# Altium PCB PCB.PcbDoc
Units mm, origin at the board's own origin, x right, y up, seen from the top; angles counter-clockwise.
Board outline 52 x 43.5 mm, 4 copper layers (Top Copper, Signal Layer 1, Signal Layer 2, Bottom Copper), stack 1.57 mm thick; 27 components, 30 nets, 106 pads, 306 vias.
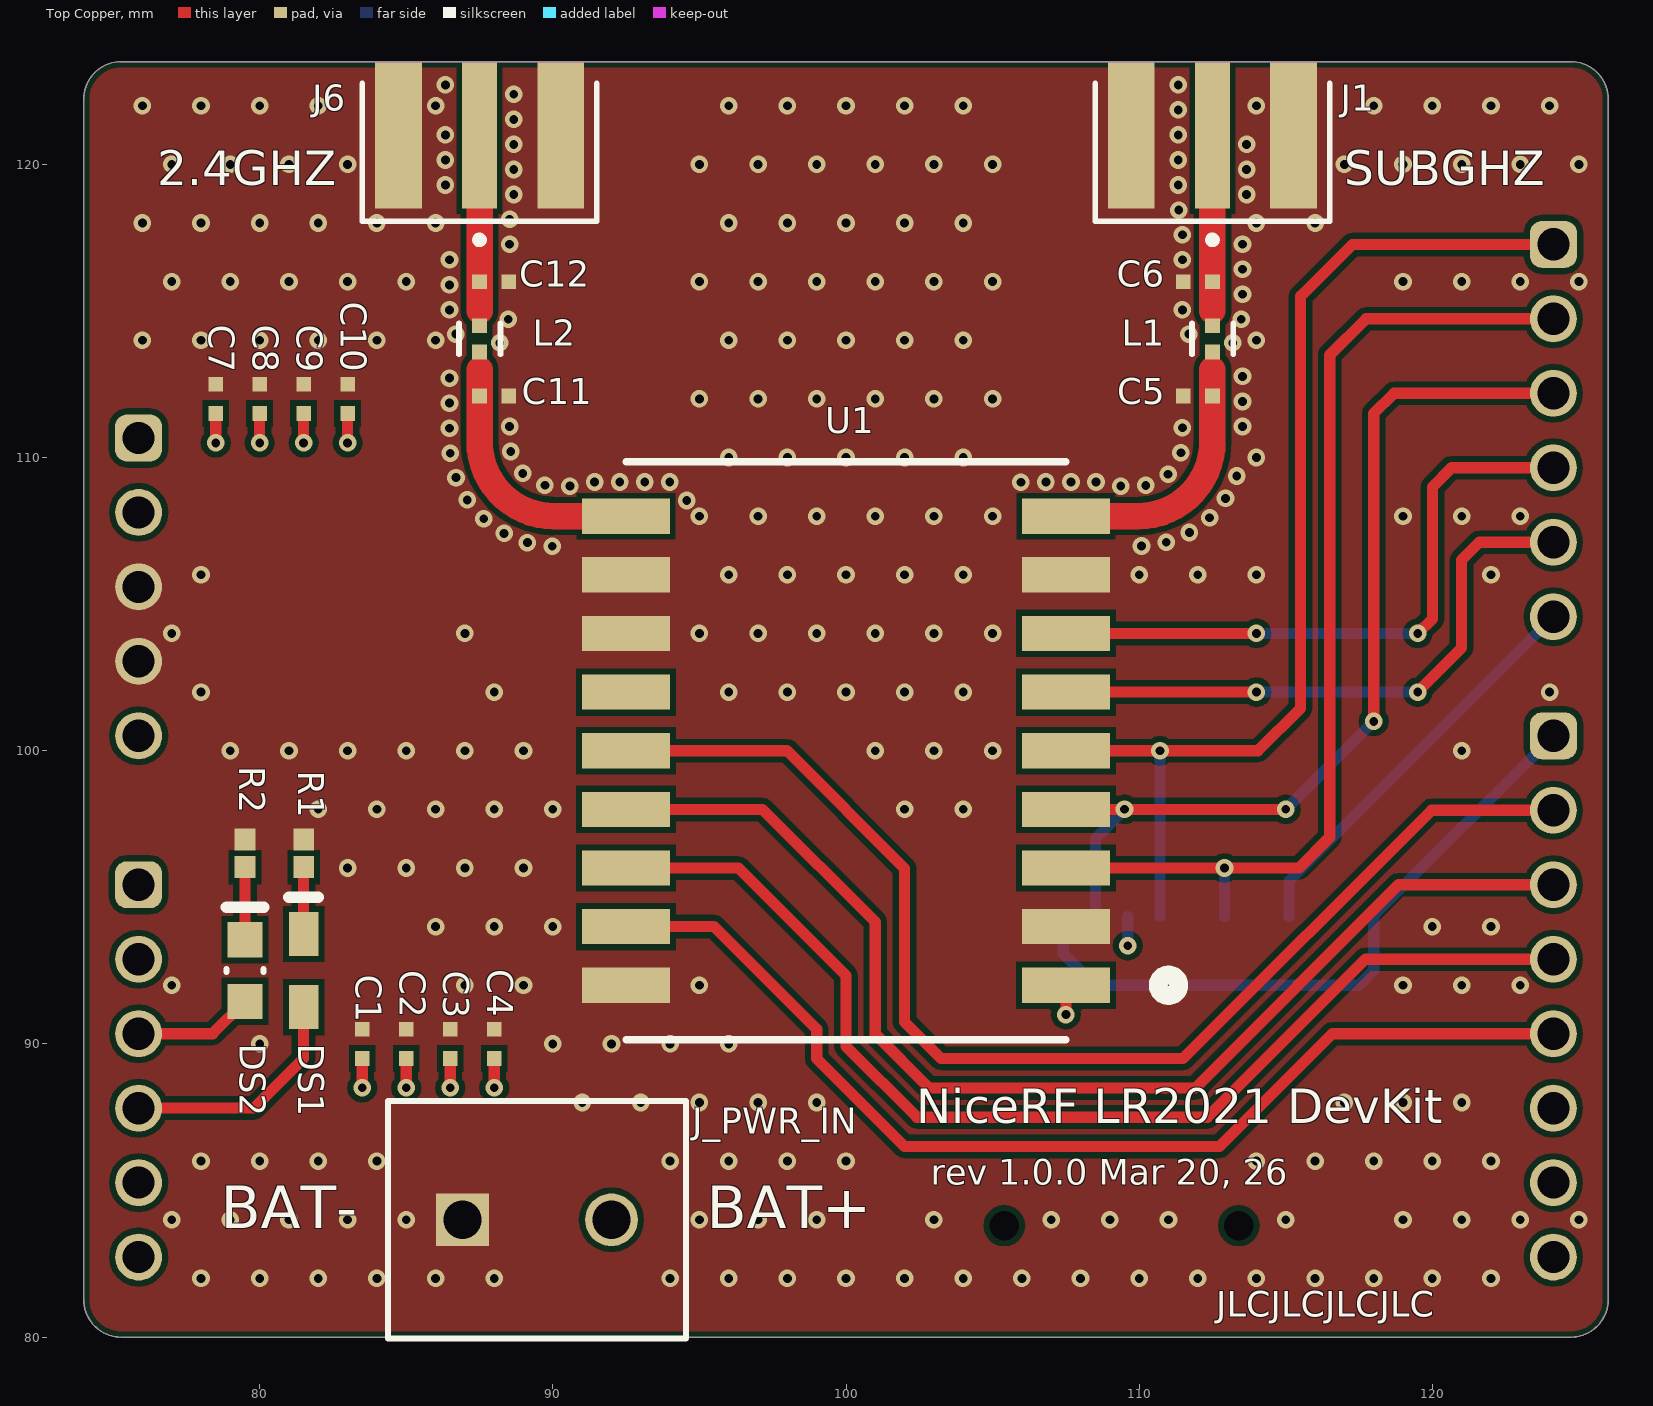
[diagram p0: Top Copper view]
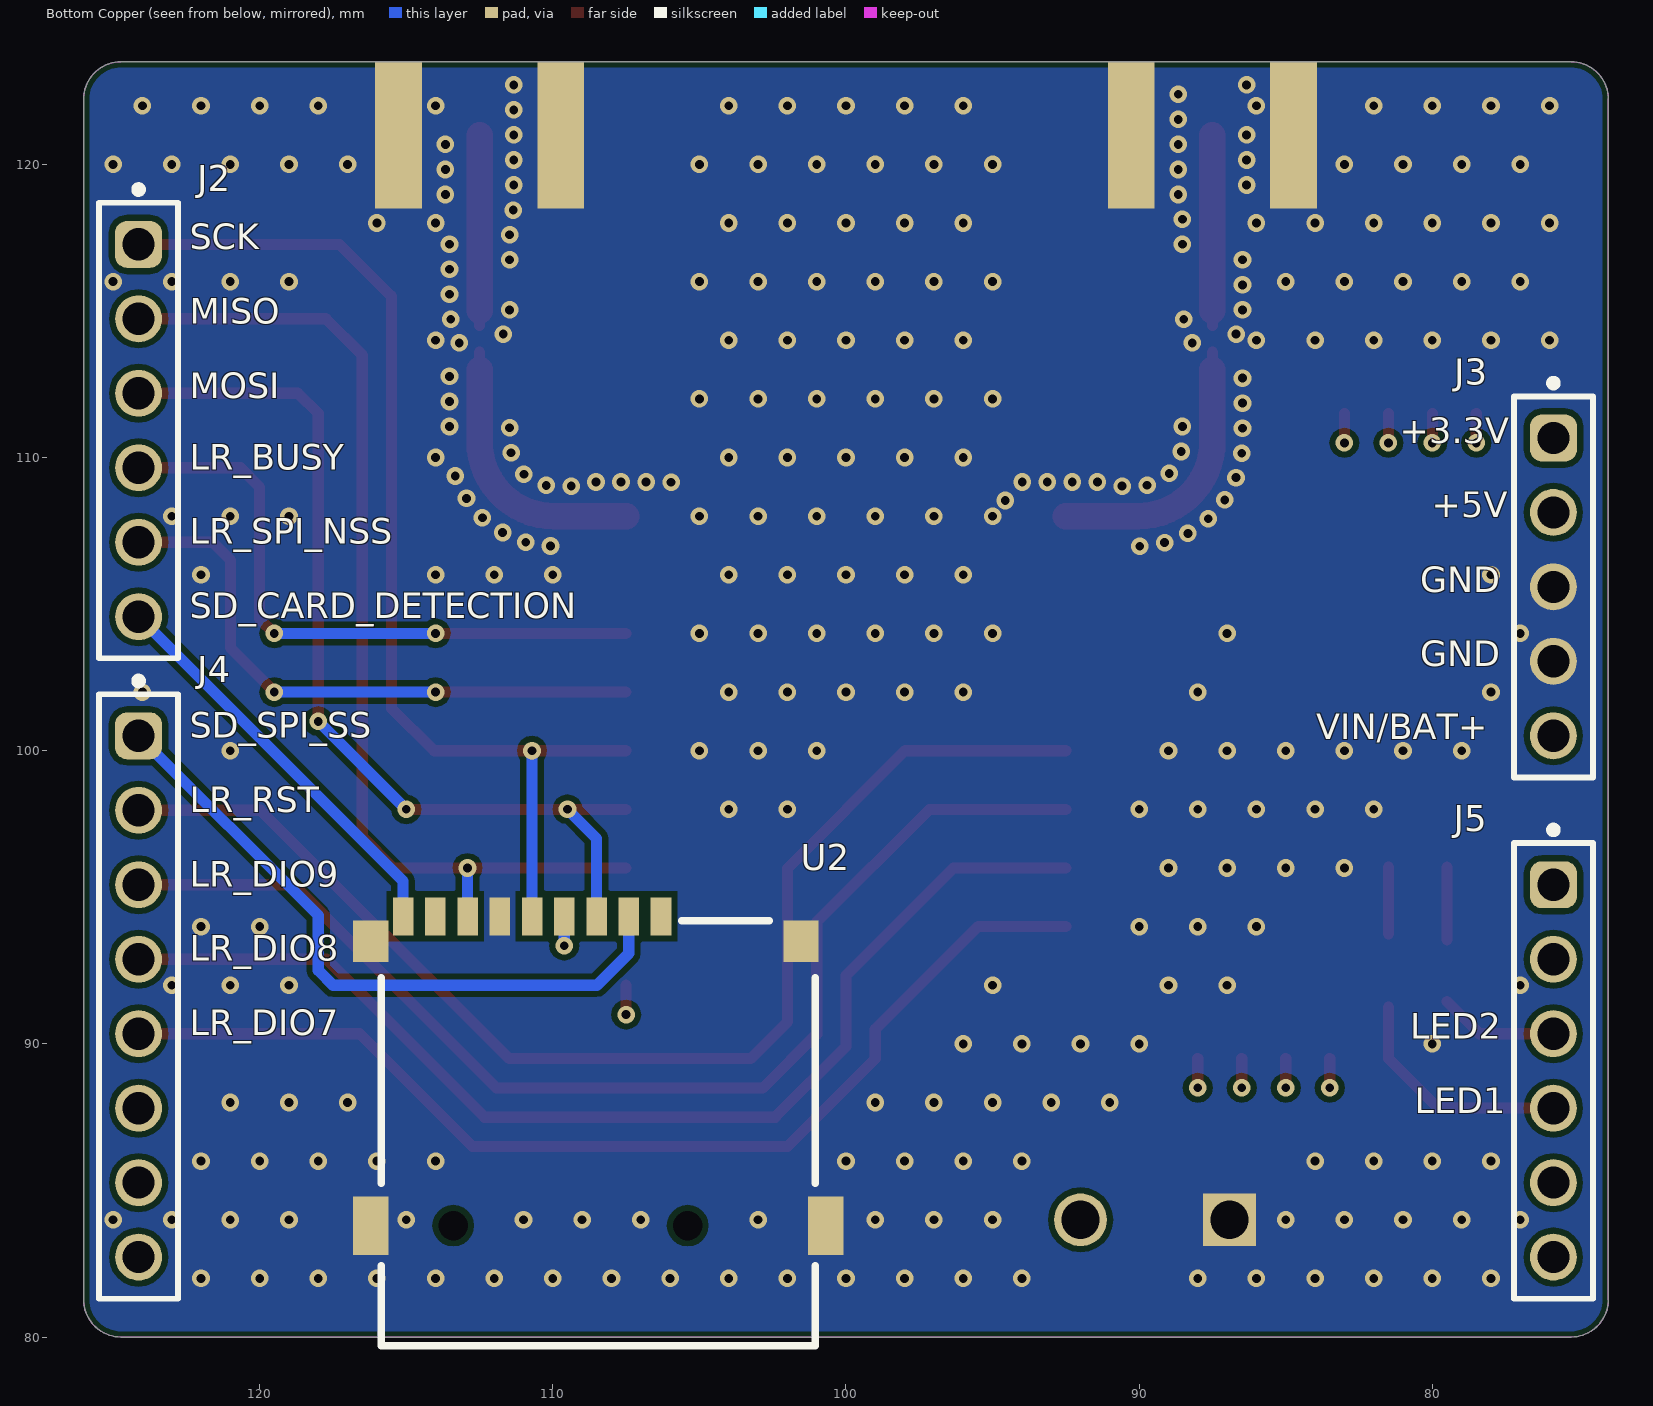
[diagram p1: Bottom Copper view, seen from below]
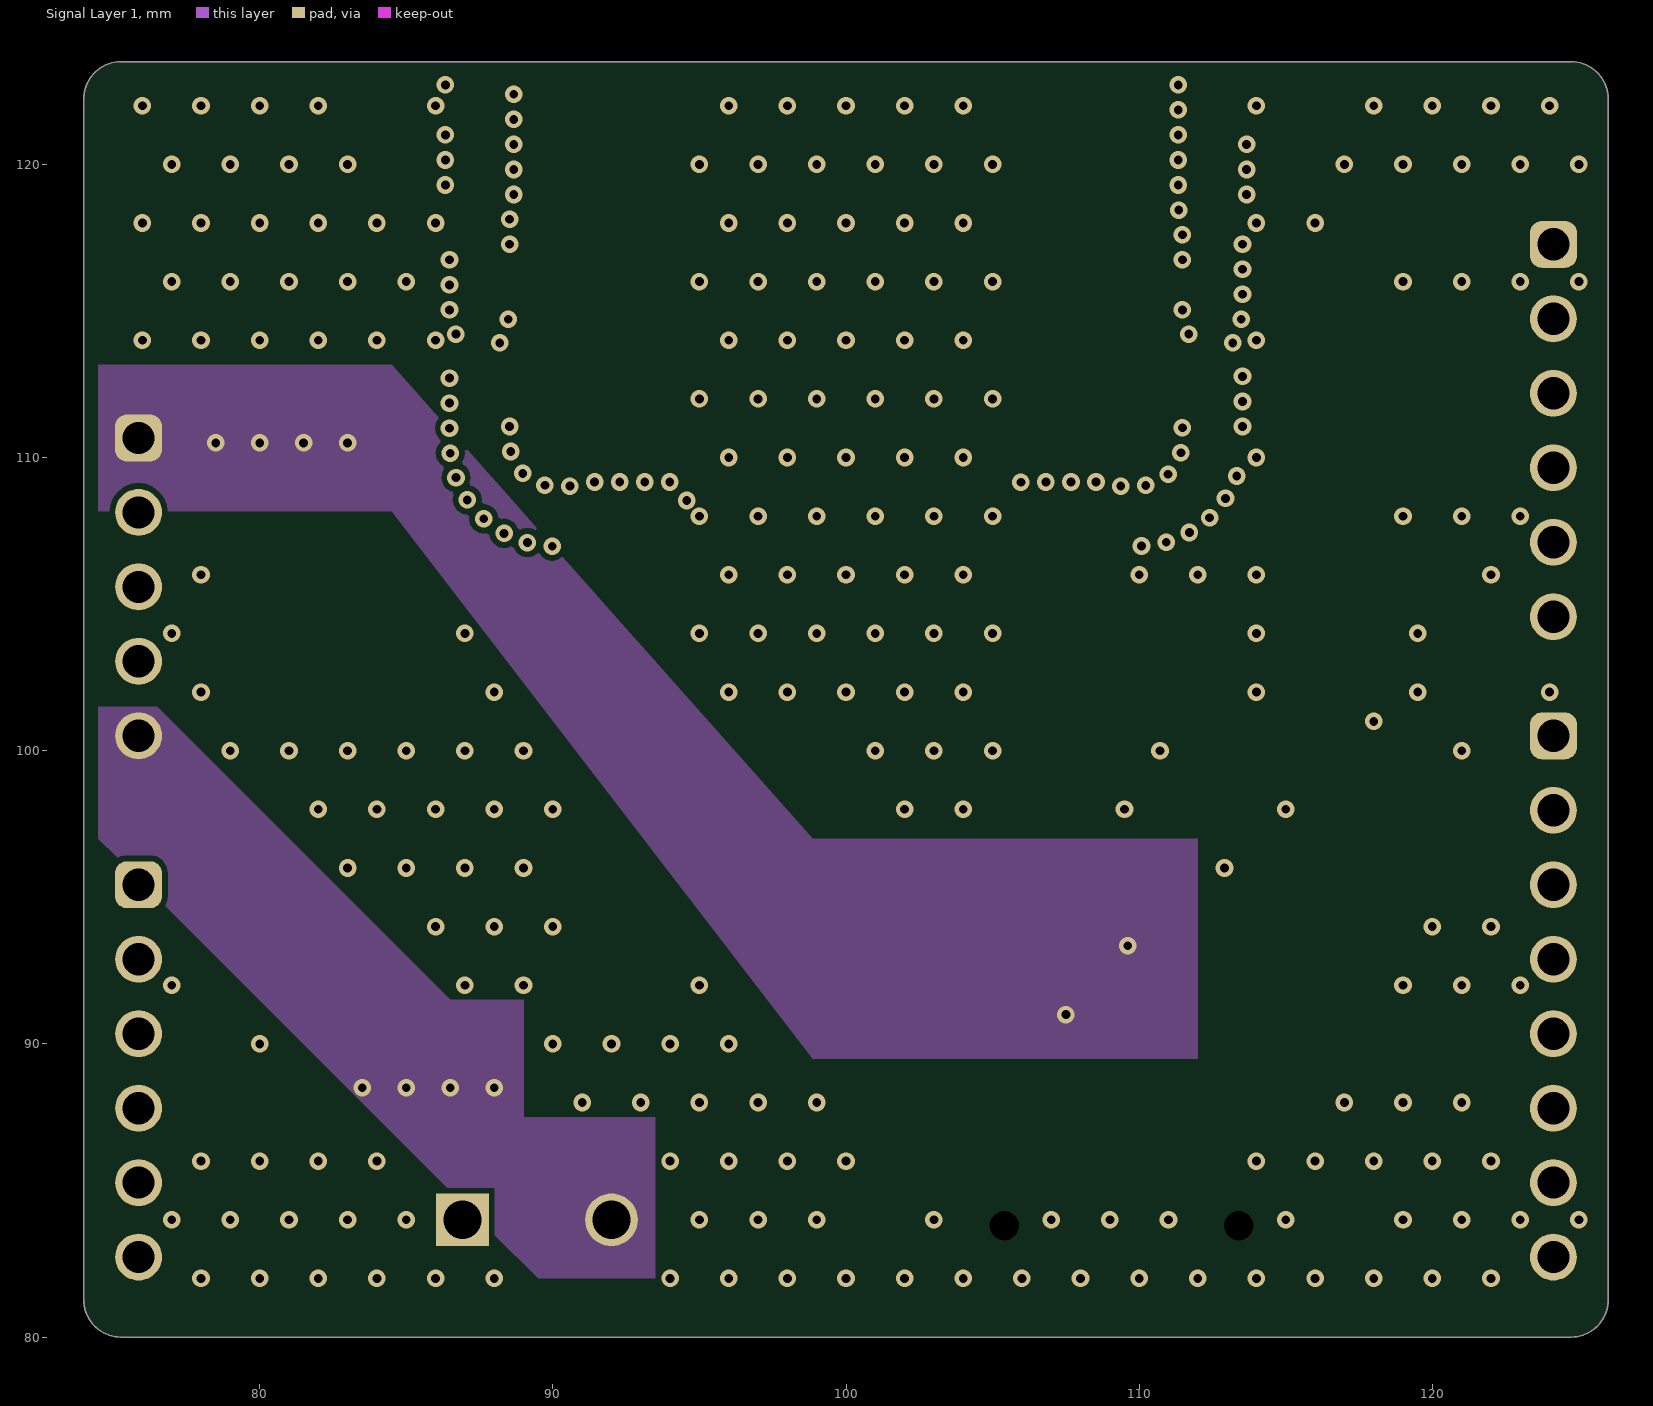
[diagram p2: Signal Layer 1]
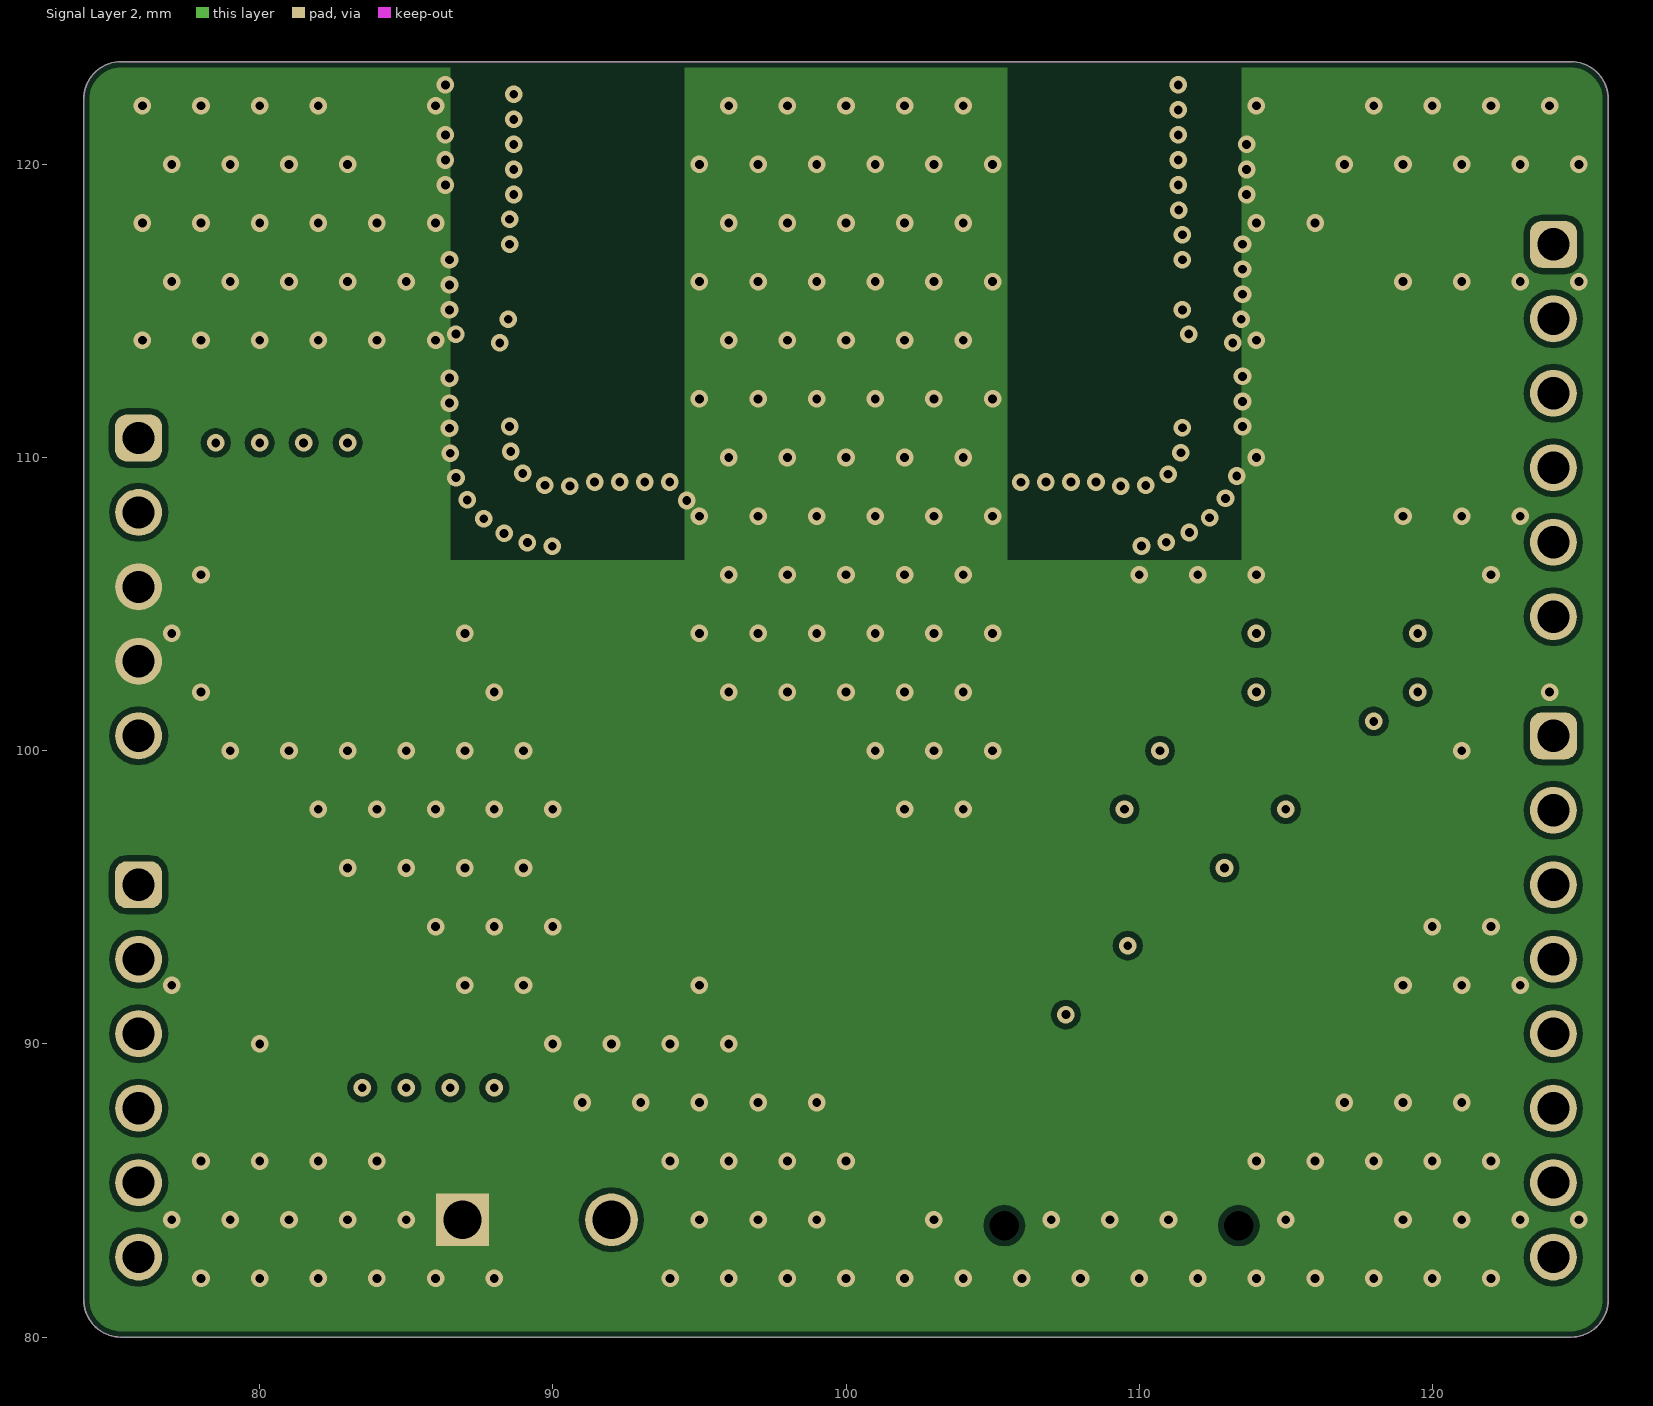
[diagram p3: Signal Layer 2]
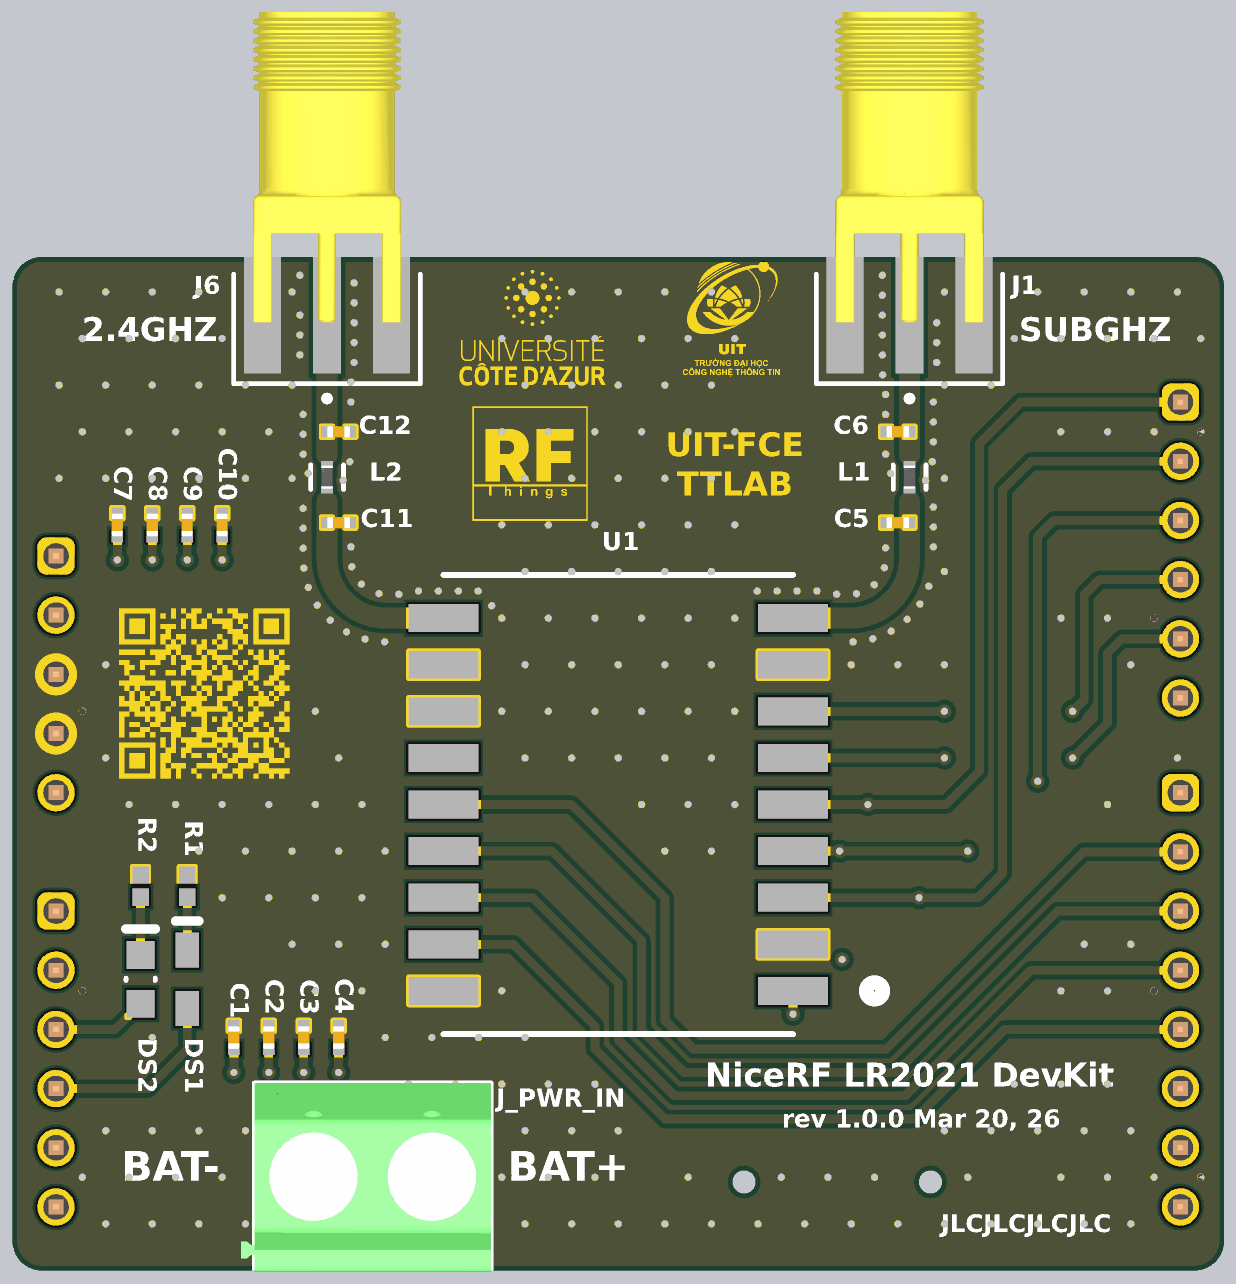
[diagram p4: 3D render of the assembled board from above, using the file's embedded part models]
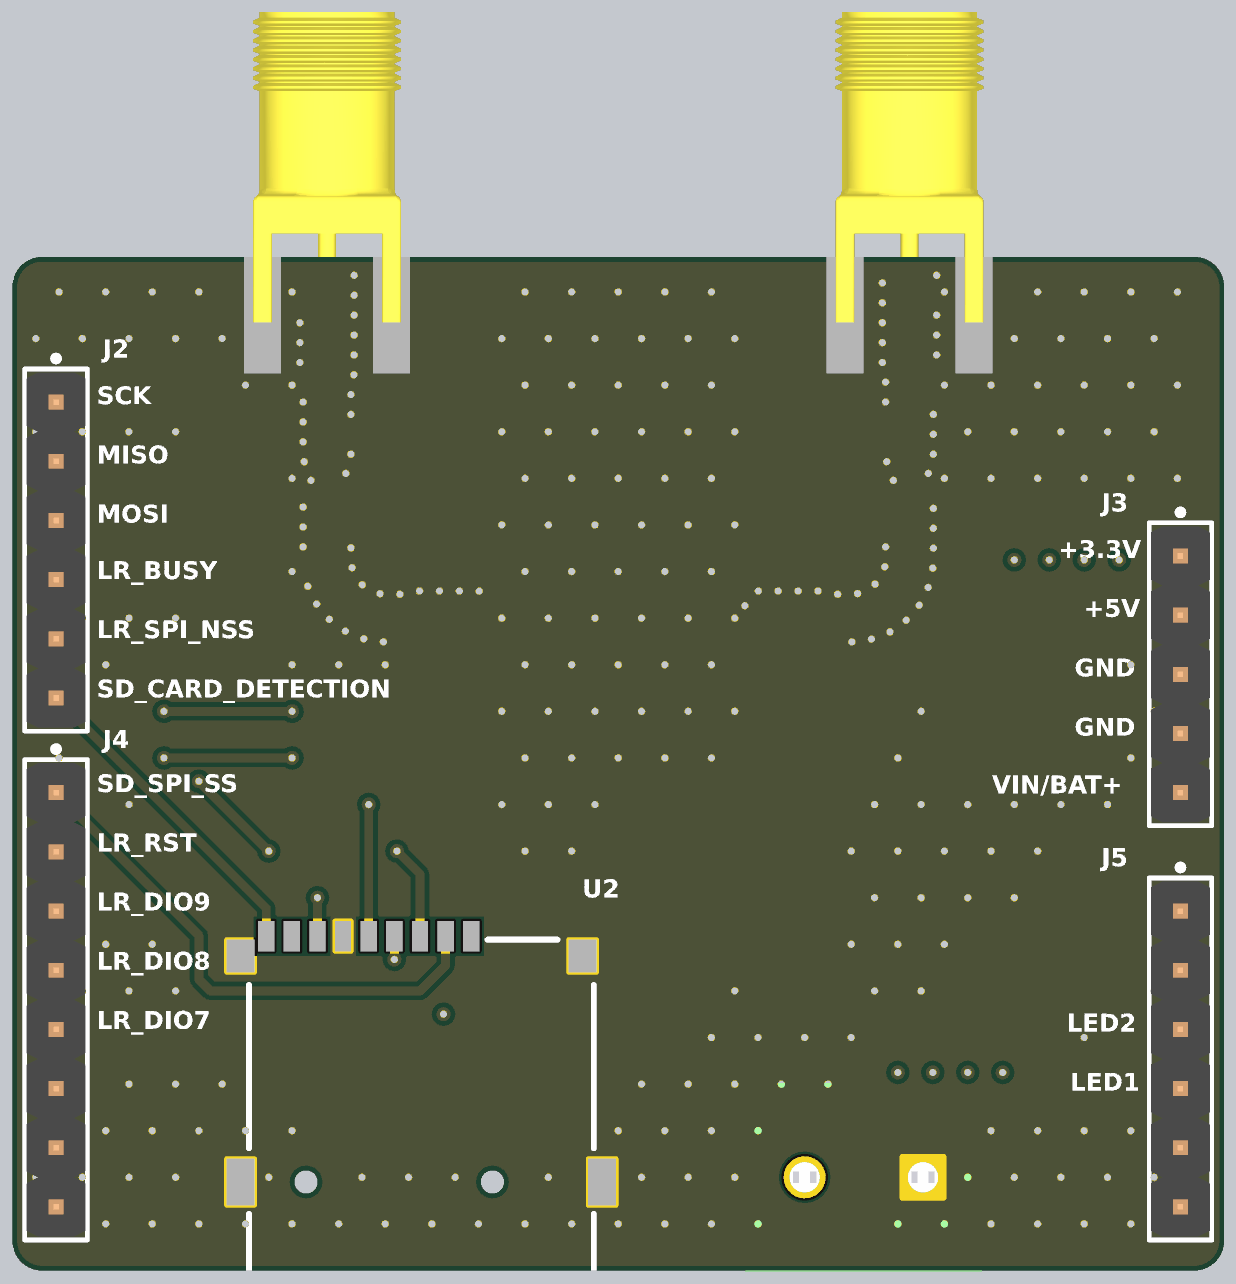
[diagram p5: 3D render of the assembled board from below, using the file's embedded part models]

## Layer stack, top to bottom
Top Mask: solder mask 0.015, Solder Resist, Dk 3.8
Top Copper: signal copper 0.035
Dielectric 1: prepreg 0.2, 7628, Dk 4.6
Signal Layer 1: signal copper 0.0175
Core: core 1.065, FR-4, Dk 4.5
Signal Layer 2: signal copper 0.0175
Dielectric 2: prepreg 0.2, 7628, Dk 4.6
Bottom Copper: signal copper 0.035
Bottom Mask: solder mask 0.015, Solder Resist, Dk 3.8

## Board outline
75.27,80 cw(c75.27,81.27) 74,81.27 74,122.23 cw(c75.27,122.23) 75.27,123.5 124.73,123.5 cw(c124.73,122.23) 126,122.23 126,81.27 cw(c124.73,81.27) 124.73,80

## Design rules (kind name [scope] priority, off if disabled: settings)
BoardOutlineClearance [All] p1: gap=0.2 ignorepadtopadclearanceinfootprint=FALSE except(0.4: Arc-SplitBarrior Arc-SplitContinuation Track-SplitBarrior Track-SplitContinuation SMDPad-SplitBarrior SMDPad-SplitContinuation THPad-SplitBarrior THPad-SplitContinuation Via-SplitBarrior Via-SplitContinuation Fill-SplitBarrior Fill-SplitContinuation Poly-SplitBarrior Poly-SplitContinuation Region-SplitBarrior Region-SplitContinuation Text-SplitBarrior Text-SplitContinuation)
Clearance [All] p1: gap=0.2 ignorepadtopadclearanceinfootprint=FALSE except(0.089: Arc-Arc Arc-Track Arc-SMDPad Track-Track Track-SMDPad SMDPad-SMDPad; 0.127: Arc-Via Track-Via SMDPad-Via THPad-Via Via-Via; 0.254: Arc-Text Track-Text SMDPad-Text THPad-Text Via-Text Fill-Text Poly-Text Region-Text Text-Text)
HoleSize [All] p1: absolutevalues=TRUE maxlimit=6.3 minlimit=0.2 maxpercent=80.000 minpercent=20.000
MinimumAnnularRing [All] p1: minimumring=0.076
MinimumSolderMaskSliver [All] p1: minsoldermaskwidth=0.1
PolygonConnect PolygonConnect_1 [All] p1: connectstyle=Direct reliefconductorwidth=0.508 reliefentries=4 polygonreliefangle="90 Angle" airgapwidth=0.254
RoutingCorners [All] p1: cornerstyle=Round minsetback=2.54 maxsetback=2.54
RoutingVias [All] p1: holewidth=0.5 width=1 viastyle="Through Hole" minholewidth=0.2 minwidth=0.45 maxholewidth=1 maxwidth=2
SilkToSilkClearance [All] p1: silktosilkclearance=0.1
SilkToSolderMaskClearance [IsPad] p1: minsilkscreentomaskgap=0.1 clearancetoexposedcopper=TRUE
SolderMaskExpansion [All] p1: expansion=0.102 istentingtop=FALSE
SupplyNets "Schematic Supply Nets_3" [InNet('+5V')] p1: voltage=0.000
SupplyNets "Schematic Supply Nets_2" [InNet('VIN')] p2: voltage=0.000
SupplyNets "Schematic Supply Nets_1" [InNet('GND')] p3: voltage=0.000
SupplyNets "Schematic Supply Nets" [InNet('+3.3V')] p4: voltage=0.000
Width [All] p1: maxlimit=2.54 minlimit=0.089 preferedwidth=0.381
25 further rules are at their usual default settings.

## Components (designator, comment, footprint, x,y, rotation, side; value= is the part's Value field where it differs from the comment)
C1 "885012205037" WCAP-CSGP_0402_L1W0.5H0.5 83.5,90 r270 top
C2 "885012205037" WCAP-CSGP_0402_L1W0.5H0.5 85,90 r270 top
C3 "885012205037" WCAP-CSGP_0402_L1W0.5H0.5 86.5,90 r270 top
C4 "885012205037" WCAP-CSGP_0402_L1W0.5H0.5 88,90 r270 top
C5 "885012205037" WCAP-CSGP_0402_L1W0.5H0.5 112,112.1 r0 top
C6 "885012205037" WCAP-CSGP_0402_L1W0.5H0.5 112,116 r0 top
C7 "885012205037" WCAP-CSGP_0402_L1W0.5H0.5 78.5,112 r270 top
C8 "885012205037" WCAP-CSGP_0402_L1W0.5H0.5 80,112 r270 top
C9 "885012205037" WCAP-CSGP_0402_L1W0.5H0.5 81.5,112 r270 top
C10 "885012205037" WCAP-CSGP_0402_L1W0.5H0.5 83,112 r270 top
C11 "885012205037" WCAP-CSGP_0402_L1W0.5H0.5 88,112.1 r180 top
C12 "885012205037" WCAP-CSGP_0402_L1W0.5H0.5 88,116 r180 top
DS1 "LTST-S220GKT" LTST-S220GKT_V 81.5,92.5 r90 top
DS2 "LTST-C170KRKT" LTST-C170KRKT_V 79.5,92.5 r90 top
J1 "CON-SMA-EDGE-S" FP-CON-SMA-EDGE-S-MFG 112.5,128.26 r0 top
J2 "61300611121" 61300611121 124.13,110.922 r270 bottom
J3 "61300511121" 61300511121 75.87,105.588 r270 bottom
J4 "61300811121" 61300811121 124.13,91.618 r270 bottom
J5 "61300611121" 61300611121 75.87,89.078 r270 bottom
J6 "CON-SMA-EDGE-S" FP-CON-SMA-EDGE-S-MFG 87.5,128.26 r0 top
J_PWR_IN "1729128" PHOE-1729128-2_V 89.46,84 r0 top
L1 "MLZ1005M1R0WT000" FP-MLZ1005-MFG 112.5,114.05 r90 top
L2 "MLZ1005M1R0WT000" FP-MLZ1005-MFG 87.5,114.05 r90 top
R1 "RT0402DRE071KL" RESC1005X35X25ML10T10 81.5,96.5 r270 top
R2 "RT0402DRE071KL" RESC1005X35X25ML10T10 79.5,96.5 r270 top
U1 "LoRa Module" LR2021 100,100 r180 top
U2 "MicroSD Slot" TF-01A 115.11,95 r180 bottom

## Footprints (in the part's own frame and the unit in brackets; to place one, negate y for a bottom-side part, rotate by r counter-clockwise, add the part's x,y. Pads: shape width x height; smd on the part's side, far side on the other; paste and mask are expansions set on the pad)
61300511121 [mm] "Pin Header, pitch 2.54 mm, THT, Vertical, single row, 5p"
  rrect50% 1.6x1.6 hole 1.1: 1(-5.08,0)
  round 1.6 hole 1.1: 2(-2.54,0) 3(0,0) 4(2.54,0) 5(5.08,0)
  silkscreen extent -7.07,-1.35 6.5,1.35, body extent -6.35,-1.27 6.35,1.27, height 8.57
61300611121 [mm] "Pin Header, pitch 2.54 mm, THT, Vertical, single row, 6p"
  rrect50% 1.6x1.6 hole 1.1: 1(-6.35,0)
  round 1.6 hole 1.1: 2(-3.81,0) 3(-1.27,0) 4(1.27,0) 5(3.81,0) 6(6.35,0)
  silkscreen extent -8.34,-1.35 7.77,1.35, body extent -7.62,-1.27 7.62,1.27, height 8.57
61300811121 [mm] "Pin Header, pitch 2.54 mm, THT, Vertical, single row, 8p"
  rrect50% 1.6x1.6 hole 1.1: 1(-8.89,0)
  round 1.6 hole 1.1: 2(-6.35,0) 3(-3.81,0) 4(-1.27,0) 5(1.27,0) 6(3.81,0) 7(6.35,0) 8(8.89,0)
  silkscreen extent -10.88,-1.35 10.31,1.35, body extent -10.16,-1.27 10.16,1.27, height 8.57
FP-CON-SMA-EDGE-S-MFG [mm]
  rect 1.2x5 smd paste+0 mask+0: 1(0,-7.26)
  rect 1.6x5 smd paste+0 mask+0: 2(-2.77,-7.26) 3(2.77,-7.26)
  rect 1.6x5 smd far side paste+0 mask+0: 4(-2.77,-7.26) 5(2.77,-7.26)
  silkscreen extent -4,-10.96 4,-5.5, body extent -3.67,-9.86 3.67,4.86, height 0.25
FP-MLZ1005-MFG [mm]
  rect 0.5x0.5 smd paste+0 mask+0: 1(-0.45,0) 2(0.45,0)
  silkscreen extent -0.53,-0.71 0.53,0.7, body extent -0.8,-0.38 0.8,0.38, height 0.25
LR2021 [mm] "LoRa2021: 160mW Multi-Band Wireless Communication Module"
  rect 3x1.2 smd: 1(-7.5,8) 2(-7.5,6) 3(-7.5,4) 4(-7.5,2) 5(-7.5,0) 6(-7.5,-2) 7(-7.5,-4) 8(-7.5,-6) 9(-7.5,-8) 10(7.5,-8) 11(7.5,-6) 12(7.5,-4) 13(7.5,-2) 14(7.5,0) 15(7.5,2) 16(7.5,4) 17(7.5,6) 18(7.5,8)
  silkscreen extent -11.35,-9.86 7.5,9.86
LTST-C170KRKT_V [mm] "SMD, 2-Leads, Body 2x1.25mm"
  rect 1.2x1.2 smd: 1(-1.05,0) 2(1.05,0)
  silkscreen extent -0.05,-0.63 2.16,0.64, body extent -1,-0.63 1,0.63, height 1.2
LTST-S220GKT_V [mm] "SMD, 2-Leads, Body 2.1x0.6mm"
  rect 1.5x1 smd: 1(-1.25,0) 2(1.25,0)
  silkscreen extent 2.5,-0.5 2.5,0.5, body extent -1.05,-0.3 1.05,0.3, height 1.1
PHOE-1729128-2_V [mm] "Receptacle, 2-Leads, Body 8.1x10.16mm, Pitch 5.08mm"
  rect 1.8x1.8 hole 1.3: 1(-2.54,0)
  round 1.8 hole 1.3: 2(2.54,0)
  silkscreen extent -5.08,-4.05 5.08,4.05, body extent -5.65,-4.05 5.08,4.05, height 10.01
RESC1005X35X25ML10T10 [mm] "Chip Resistor, 2-Leads, Body 1.00x0.50mm, IPC Low Density"
  rect 0.75x0.7 smd: 1(-0.475,0) 2(0.475,0)
  body extent -0.55,-0.3 0.55,0.3, height 0.35
TF-01A [mm]
  rect 0.7x1.3 smd: 1(8.8,-0.65) 2(7.7,-0.65) 3(6.6,-0.65) 4(5.5,-0.65) 5(4.4,-0.65) 6(3.3,-0.65) 7(2.2,-0.65) 8(1.1,-0.65) 9(0,-0.65)
  rect 1.2x1.4 smd: 10(-1.1,-1.5) 13(13.58,-1.5)
  rect 1.2x2 smd: 11(-1.1,-11.2) 12(14.42,-11.2)
  rect 0x0 hole 1 unplated: 14(1.71,-11.2) 15(9.71,-11.2)
  silkscreen extent -0.74,-15.3 14.06,-0.8
WCAP-CSGP_0402_L1W0.5H0.5 [mm] "Ceramic Capacitors, body 1x0.5mm"
  rect 0.5x0.5 smd: 1(-0.5,0) 2(0.5,0)
  body extent -0.5,-0.25 0.5,0.25, height 0.5

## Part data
C1 C2 C3 C4 C5 C6 C7 C8 C9 C10 C11 C12: library part CMP-207839-000001-3, "Cap Ceramic 0.1uF 16V X7R 10% Pad SMD 0402 125C T/R", Capacitance=100nF, Case Code (Imperial)=0402, Case Code (Metric)=1005, Dielectric=X7R, Insulation Resistance=5GΩ, Max Operating Temperature=125°C, Min Operating Temperature=-55°C, Tolerance=10%, Voltage Rating=16V
DS1: library part CMP-2000-06627-1, "LED Green, 100 mW, 30 mA, -55 to 85 degC, 2-Pin SMD, RoHS, Tape and Reel", Emitting Color=YellowGreen, Forward Current=30mA, Forward Voltage=2.6V, Manufacturer=Lite-On, Operating Temp Range=-55Cto85C, Operating Temperature Classification=Industrial, Package Description="2-Pin Surface Mount Device, Body 2.1 x 0.6 mm", Package Reference=S220GKT, Package Type=SMD, Power Dissipation=100W, Reverse Voltage=5V, Test Current (It)=20mA
DS2: library part CMP-2000-07593-1, "LED Red, 75 mW, 54 mcd, -55 to 85 degC, 2-Pin SMD, RoHS, Tape and Reel", Case Code (Imperial)=0805, Case Code (Metric)=2012, Colour=Red, Forward Current=30mA, Forward Voltage=2V, Lens Colour=Colorless, Manufacturer=Lite-On, Max Operating Temperature=85degC, Min Operating Temperature=-55degC, Package Description="2-Pin Surface Mount Device, Body 2 x 1.25 mm", Package Quantity=1, Package Reference=C170KRKT, Power Dissipation=75mW, Test Current=20mA
J1 J6: library part CMP-204357-000001-1, "CONN SMA JACK STR EDGE MNT", Frequency=18GHz, Manufacturer="RF Solutions Ltd.", Package=CONN_JACK
J2 J5: library part CMP-1502-01070-4, "THT Vertical Pin Header WR-PHD, Pitch 2.54 mm, Single Row, 6 pins", Color=Black, Contact Resistance=20mΩ, Current Rating=3A, Max Operating Temperature=105°C, Min Operating Temperature=-40°C, Operating Supply Voltage=250V
J3: library part CMP-1502-01068-4, "THT Vertical Pin Header WR-PHD, Pitch 2.54 mm, Single Row, 5 pins", Color=Black, Contact Resistance=20mΩ, Current Rating=3A, Max Operating Temperature=105°C, Min Operating Temperature=-40°C, Operating Supply Voltage=250V
J4: library part CMP-1502-01076-4, "THT Vertical Pin Header WR-PHD, Pitch 2.54 mm, Single Row, 8 pins", Color=Black, Contact Resistance=20mΩ, Current Rating=3A, Max Operating Temperature=105°C, Min Operating Temperature=-40°C, Operating Supply Voltage=250V
J_PWR_IN: library part CMP-2000-05815-1, "PCB Terminal Block, 13.5 A, 400 V, 2-Pin THD, RoHS, Bulk", Current Rating=13500mA, Manufacturer="Phoenix Contact", Package Description="2-Pin Through Hole Device, Body 8.1 x 10.16 mm, Pitch 5.08 mm", Package Reference=1729128-2, Package Version=03/2015, Voltage Rating=400V
L1 L2: library part CMP-08253-000219-1, "Shielded Multilayer Inductor 1uH ±20% 450mA 455mΩ SMD 0402", Case Code (Imperial)=0402, Case Code (Metric)=1005, Current Rating=450mA, DC Resistance (DCR)=455mR, Inductance=1uH, Max Operating Temperature=125°C, Min Operating Temperature=-55°C, Package Quantity=10000, Saturation Current=100mA, Self Resonant Frequency=170MHz, Test Frequency=2MHz, Tolerance=20%
R1 R2: library part CMP-2002-02598-1, Manufacturer=Yageo
U1: library part LR2021, "LoRa2021: 160mW Multi-Band Wireless Communication Module"
U2: library part TF-01A, "1.85mm Card Slot MicroSD card (TF card) Self-bouncing SMD SD Card / Memory Card Connector ROHS"

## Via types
v1: diameter 0.6, hole 0.3, Top Copper to Bottom Copper, tented both sides, 306 vias

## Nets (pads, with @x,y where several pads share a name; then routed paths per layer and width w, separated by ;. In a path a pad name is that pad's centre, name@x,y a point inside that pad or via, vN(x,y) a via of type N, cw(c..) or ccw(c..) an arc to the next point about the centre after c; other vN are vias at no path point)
2.4GHZ_ANT: C11.2 L2.1 U1.10 | length 10.4
  Top Copper w0.381: C11.2 L2.1
  Top Copper w0.904: 87.5,113 87.5,110.54 ccw(c90.04,110.54) 90.04,108 U1.10
+3.3V: C7.2 C8.2 C9.2 C10.2 J3.1 U1.1 U2.4 | length 6
  Top Copper w0.381: v1(78.5,110.5) C7.2 ; v1(80,110.5) C8.2 ; v1(81.5,110.5) C9.2 ; v1(83,110.5) C10.2 ; v1(107.5,91) U1.1
  Bottom Copper w0.381: v1(109.61,93.35) U2.4
+5V: J3.2
ADR_A0: J5.1
ADR_A1: J5.2
ADR_A2: DS2.1 J5.3 | length 4.1
  Top Copper w0.381: J5.3 78.398,90.348 DS2.1
ADR_A3: DS1.1 J5.4 | length 8.1
  Top Copper w0.381: J5.4 79.808,87.808 81.5,89.5 DS1.1
ADR_A4: J5.5
ADR_A5: J5.6
ADR_D0: J4.8
ADR_D1: J4.7
ADR_D2: J4.6
ADR_D3: J4.5 U1.17 | length 36.9
  Top Copper w0.381: U1.17 95.5,94 99,90.5 99,89.5 102,86.5 112.743,86.5 116.591,90.348 J4.5
ADR_D4: J4.4 U1.16 | length 38.8
  Top Copper w0.381: U1.16 96.328,96 100,92.328 100,89.914 102.414,87.5 112.328,87.5 117.716,92.888 J4.4
ADR_D5: J4.3 U1.15 | length 40.7
  Top Copper w0.381: U1.15 97.157,98 101,94.157 101,90.328 102.828,88.5 111.914,88.5 118.842,95.428 J4.3
ADR_D6: J4.2 U1.14 | length 42.6
  Top Copper w0.381: U1.14 97.985,100 102,95.985 102,90.743 103.243,89.5 111.5,89.5 119.968,97.968 J4.2
ADR_D7: J4.1 U2.2 | length 23.1
  Bottom Copper w0.381: U2.2 107.41,93.09 108.5,92 117.5,92 118,92.5 118,94.378 J4.1
ADR_D8: J2.6 U2.9 | length 14
  Bottom Copper w0.381: U2.9 115.11,95.552 J2.6
ADR_D9: J2.5 U1.6 | length 20.5
  Top Copper w0.381: U1.6 v1(114,102) ; v1(119.5,102) 121,103.5 121,106.5 121.612,107.112 J2.5
  Bottom Copper w0.381: v1(114,102) v1(119.5,102)
ADR_D10: J2.4 U1.7 | length 21.6
  Top Copper w0.381: U1.7 v1(114,104) ; v1(119.5,104) 120,104.5 120,109 120.652,109.652 J2.4
  Bottom Copper w0.381: v1(114,104) v1(119.5,104)
ADR_D11: J2.3 U1.4 U2.3 | length 32.7
  Top Copper w0.381: U1.4 v1(109.5,98) v1(115,98) ; v1(118,101) 118,111.5 118.692,112.192 J2.3
  Bottom Copper w0.381: U2.3 108.51,97.01 v1(109.5,98) ; v1(115,98) v1(118,101)
ADR_D12: J2.2 U1.3 U2.7 | length 35.7
  Top Copper w0.381: U1.3 v1(112.91,96) 115.452,96 116.5,97.048 116.5,113.5 117.732,114.732 J2.2
  Bottom Copper w0.381: U2.7 v1(112.91,96)
ADR_D13: J2.1 U1.5 U2.5 | length 37.7
  Top Copper w0.381: U1.5 v1(110.71,100) 114.059,100 115.5,101.441 115.5,115.5 117.272,117.272 J2.1
  Bottom Copper w0.381: U2.5 v1(110.71,100)
GND: C1.1 C2.1 C3.1 C4.1 C5.1 C6.1 C7.1 C8.1 C9.1 C10.1 C11.1 C12.1 J1.2 J1.3 J1.4 J1.5 J3.3 J3.4 J6.2 J6.3 J6.4 J6.5 J_PWR_IN.1 R1.1 R2.1 U1.2 U1.8 U1.11 U1.12 U1.18 U2.6 U2.10 U2.11 U2.12 U2.13
  other v1: 78,82 80,82 82,82 84,82 86,82 88,82 94,82 96,82 98,82 100,82 102,82 104,82 106,82 108,82 110,82 112,82 114,82 116,82 118,82 120,82 122,82 77,84 79,84 81,84 83,84 85,84 95,84 97,84 99,84 103,84 107,84 109,84 111,84 115,84 119,84 121,84 123,84 125,84 78,86 80,86 82,86 84,86 94,86 96,86 98,86 100,86 114,86 116,86 118,86 120,86 122,86 91,88 93,88 95,88 97,88 99,88 117,88 119,88 121,88 80,90 90,90 92,90 94,90 96,90 77,92 87,92 89,92 95,92 119,92 121,92 123,92 86,94 88,94 90,94 120,94 122,94 83,96 85,96 87,96 89,96 82,98 84,98 86,98 88,98 90,98 102,98 104,98 79,100 81,100 83,100 85,100 87,100 89,100 101,100 103,100 105,100 121,100 78,102 88,102 96,102 98,102 100,102 102,102 104,102 124,102 77,104 87,104 95,104 97,104 99,104 101,104 103,104 105,104 78,106 96,106 98,106 100,106 102,106 104,106 110,106 112,106 114,106 122,106 89.977,106.977 110.08,106.982 89.132,107.1 110.924,107.113 88.337,107.412 111.712,107.442 87.643,107.91 112.401,107.947 95,108 97,108 99,108 101,108 103,108 105,108 119,108 121,108 123,108 94.565,108.535 87.084,108.556 112.946,108.604 90.583,109.026 109.371,109.026 110.224,109.048 89.73,109.056 91.426,109.165 92.28,109.165 93.134,109.165 93.988,109.165 105.966,109.158 106.82,109.165 107.674,109.165 108.528,109.165 86.697,109.317 113.325,109.369 110.988,109.43 88.977,109.458 96,110 98,110 100,110 102,110 104,110 114,110 86.503,110.149 111.424,110.164 88.563,110.205 86.474,111.002 111.474,111.017 88.526,111.059 113.526,111.059 86.474,111.856 113.526,111.913 95,112 97,112 99,112 101,112 103,112 105,112 86.474,112.71 113.526,112.767 88.19,113.912 113.19,113.912 76,114 78,114 80,114 82,114 84,114 86,114 96,114 98,114 100,114 102,114 104,114 114,114 86.693,114.21 111.693,114.21 88.48,114.715 113.48,114.715 86.474,115.035 111.474,115.035 113.526,115.568 86.474,115.889 77,116 79,116 81,116 83,116 85,116 95,116 97,116 99,116 101,116 103,116 105,116 119,116 121,116 123,116 125,116 113.526,116.422 86.474,116.743 111.474,116.743 88.526,117.276 113.526,117.276 111.474,117.597 76,118 78,118 80,118 82,118 84,118 86,118 96,118 98,118 100,118 102,118 104,118 114,118 116,118 88.526,118.13 111.347,118.442 88.665,118.972 113.665,118.972 86.335,119.296 111.335,119.296 88.665,119.826 113.665,119.826 77,120 79,120 81,120 83,120 95,120 97,120 99,120 101,120 103,120 105,120 117,120 119,120 121,120 123,120 125,120 86.335,120.15 111.335,120.15 88.665,120.68 113.665,120.68 86.335,121.004 111.335,121.004 88.665,121.534 111.335,121.858 76,122 78,122 80,122 82,122 86,122 96,122 98,122 100,122 102,122 104,122 114,122 118,122 120,122 122,122 124,122 88.665,122.388 86.335,122.712 111.335,122.712
NetC6_2: C6.2 J1.1 L1.2 | length 7.5
  Top Copper w0.381: L1.2 C6.2
  Top Copper w0.904: 112.5,115 J1.1
NetC12_2: C12.2 J6.1 L2.2 | length 7.5
  Top Copper w0.381: L2.2 C12.2
  Top Copper w0.904: 87.5,115 J6.1
NetDS1_2: DS1.2 R1.2 | length 2.3
  Top Copper w0.381: DS1.2 R1.2
NetDS2_2: DS2.2 R2.2 | length 2.5
  Top Copper w0.381: DS2.2 R2.2
SUBGHZ_ANT: C5.2 L1.1 U1.9 | length 10.4
  Top Copper w0.381: C5.2 L1.1
  Top Copper w0.904: U1.9 109.96,108 ccw(c109.96,110.54) 112.5,110.54 112.5,113
VIN: C1.2 C2.2 C3.2 C4.2 J3.5 J_PWR_IN.2 | length 4
  Top Copper w0.381: v1(83.5,88.5) C1.2 ; v1(85,88.5) C2.2 ; v1(86.5,88.5) C3.2 ; v1(88,88.5) C4.2
pads on no net: U1.13 U2.1 U2.8 U2.14 U2.15

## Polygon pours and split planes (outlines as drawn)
VIN on Signal Layer 1 "Signal Layer 1-VIN" (solid, pour order 2): 86.5,91.5 76.5,101.5 74.5,101.5 74.5,97 89.5,82 93.5,82 93.5,87.5 89,87.5 89,91.5
+3.3V on Signal Layer 1 "Signal Layer 1-+3.3V" (solid, pour order 1): 74.5,108.168 74.5,113.168 84.5,113.168 98.87,97 112,97 112,89.5 98.87,89.5 84.5,108.168
GND on Bottom Copper "Bottom Copper-GND" (solid, pour order 3): 74,81.27 74,122.23 cw(c75.27,122.23) 75.27,123.5 124.73,123.5 cw(c124.73,122.23) 126,122.23 126,81.27 cw(c124.73,81.27) 124.73,80 75.27,80 cw(c75.27,81.27)
GND on Top Copper "Top Copper-GND" (solid, pour order 0): 74,81.27 74,122.23 cw(c75.27,122.23) 75.27,123.5 124.73,123.5 cw(c124.73,122.23) 126,122.23 126,81.27 cw(c124.73,81.27) 124.73,80 75.27,80 cw(c75.27,81.27)
GND on Signal Layer 2 "Signal Layer 2-GND" (solid, pour order 4): 74,81.27 74,122.23 cw(c75.27,122.23) 75.27,123.5 124.73,123.5 cw(c124.73,122.23) 126,122.23 126,81.27 cw(c124.73,81.27) 124.73,80 75.27,80 cw(c75.27,81.27)

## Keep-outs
Keep-Out Layer:
  the board outline again, w0.025

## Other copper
Signal Layer 2:
  pour cut-out: 113.5,106.5 105.5,106.5 105.5,123.5 113.5,123.5
  pour cut-out: 86.5,106.5 94.5,106.5 94.5,123.5 86.5,123.5

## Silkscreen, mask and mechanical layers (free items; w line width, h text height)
Top Overlay:
  text "2.4GHZ" at 76.504,118.902 h2
  text "SUBGHZ" at 117,118.902 h2
  text "NiceRF LR2021 DevKit" at 102.399,86.902 h2
  text "rev 1.0.0 Mar 20, 26" at 102.899,84.902 h1.5
  text "BAT-" at 78.677,83.229 h2.5
  text "BAT+" at 95.25,83.229 h2.5
  text "JLCJLCJLCJLC" at 112.624,80.402 h1.5
Bottom Overlay:
  text "SCK" at 122.38,116.807 h1.5
  text "MISO" at 122.38,114.267 h1.5
  text "MOSI" at 122.38,111.727 h1.5
  text "+3.3V" at 81.111,110.204 h1.5
  text "LR_BUSY" at 122.38,109.302 h1.5
  text "+5V" at 80.023,107.675 h1.5
  text "LR_SPI_NSS" at 122.38,106.762 h1.5
  text "GND" at 80.419,105.123 h1.5
  text "SD_CARD_DETECTION" at 122.38,104.222 h1.5
  text "GND" at 80.419,102.583 h1.5
  text "SD_SPI_SS" at 122.38,100.158 h1.5
  text "VIN/BAT+" at 83.959,100.109 h1.5
  text "LR_RST" at 122.38,97.618 h1.5
  text "LR_DIO9" at 122.38,95.077 h1.5
  text "LR_DIO8" at 122.38,92.538 h1.5
  text "LR_DIO7" at 122.38,89.998 h1.5
  text "LED2" at 80.75,89.881 h1.5
  text "LED1" at 80.598,87.346 h1.5
Top Mask:
  drawing of 202 lines, arcs and shapes, not listed
  text "UIT-FCE / TTLAB" at 101.452,112.849 h2
Mechanical 1:
  lines w0.025: 86.5,106.5 94.5,106.5 94.5,123.5 86.5,123.5 86.5,106.5
  lines w0.254: 74,81.27 ccw(c75.27,81.27) 75.27,80 ; 74,122.23 cw(c75.27,122.23) 75.27,123.5 ; 124.73,80 ccw(c124.73,81.27) 126,81.27 ; 124.73,123.5 cw(c124.73,122.23) 126,122.23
